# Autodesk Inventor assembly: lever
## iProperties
Author: E. MOSS
Created: 2001-10
Part Number: lever
Document SubType Name: Assembly
Designer: E. MOSS
Control State: 0
Master: False
Checked Out: False
PropertySet Name: Design Tracking Control
Shininess: 64.0
Angle Display Precision: 2
Document Length Units: 11272
Document Angle Units: 11286
Document Time Units: 11279
Document Mass Units: 11290
Document Length Units Precision: 3
Document Angle Units Precision: 2
Compacted: False
PropertySet Name: _Private Model Information
Density: 0.0
Volumn: 0.0
Area: 0.0
PropertySet Name: Model Information
